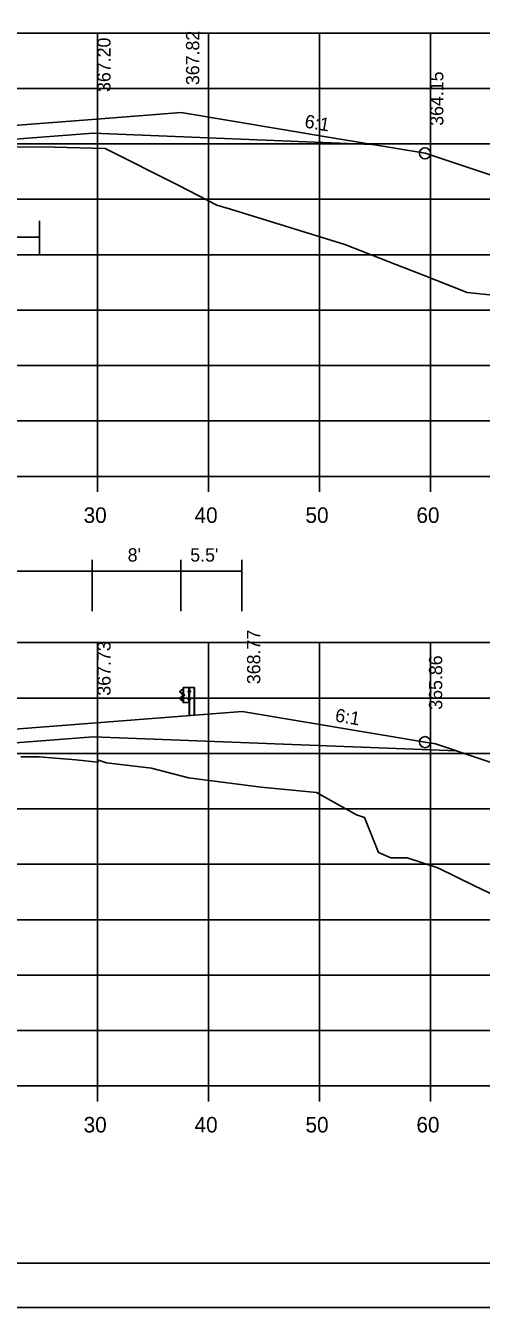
# Model space of a CAD drawing. Extents: x 1374859 to 1376773, y 382242 to 389804.
# Drawn here: x 1376158.1 to 1376199.2, y 384161.8 to 384277.4 of the extents above; entities that cross this region are included whole.
import ezdxf

# ---------------------------------------------------------------- set-up
doc = ezdxf.new("R2010")
doc.units = 0
for name, color, linetype in [('R_Axis', 7, 'Continuous'), ('R_Axis Annot', 7, 'Continuous'), ('R_Border', 7, 'Continuous'), ('R_Border Notes', 7, 'Continuous'), ('R_Exist Surface', 7, 'Continuous'), ('R_Fin Surface', 7, 'Continuous'), ('R_Grid', 7, 'Continuous'), ('R_MOT', 7, 'Continuous'), ('R_No Plot', 7, 'Continuous'), ('R_Proposed Road', 7, 'Continuous'), ('R_Xsect Elev', 7, 'Continuous'), ('R_Xsect Slope', 7, 'Continuous')]:
    doc.layers.add(name, color=color, linetype=linetype)

msp = doc.modelspace()

# ---------------------------------------------------------------- linework, layer by layer
at = {"layer": 'R_Axis'}
for p, q in [((1375994.57, 384236.76), (1376274.57, 384236.76)), ((1376164.57, 384235.36), (1376164.57, 384236.76)), ((1376174.57, 384235.36), (1376174.57, 384236.76)), ((1376184.57, 384235.36), (1376184.57, 384236.76)), ((1376194.57, 384235.36), (1376194.57, 384236.76)), ((1375994.57, 384181.76), (1376274.57, 384181.76)), ((1376164.57, 384180.36), (1376164.57, 384181.76)), ((1376174.57, 384180.36), (1376174.57, 384181.76)), ((1376184.57, 384180.36), (1376184.57, 384181.76)), ((1376194.57, 384180.36), (1376194.57, 384181.76))]:
    msp.add_line(p, q, dxfattribs=at)
at = {"layer": 'R_Border'}
msp.add_line((1376292.75, 384165.76), (1375976.57, 384165.76), dxfattribs=at)
at = {"layer": 'R_Border Notes'}
for points in [[(1376159.34, 384259.83), (1376159.34, 384256.83)], [(1376135.33, 384258.33), (1376159.34, 384258.33)]]:
    msp.add_lwpolyline(points, dxfattribs=at)
at = {"layer": 'R_Exist Surface'}
for points in [[(1376157.2, 384266.45), (1376159.53, 384266.49), (1376162.96, 384266.41), (1376165.25, 384266.35), (1376171.88, 384262.99), (1376175.32, 384261.23), (1376176.54, 384260.87), (1376186.87, 384257.69), (1376191.47, 384255.88), (1376193.87, 384254.93), (1376197.9, 384253.35), (1376203.67, 384252.75)], [(1376157.66, 384211.44), (1376158.17, 384211.44), (1376159.3, 384211.44), (1376162.61, 384211.18), (1376164.59, 384210.97), (1376164.65, 384211.16), (1376165.38, 384210.92), (1376169.44, 384210.43), (1376172.76, 384209.56), (1376179.31, 384208.72), (1376184.3, 384208.22), (1376187.91, 384206.23), (1376188.63, 384205.98), (1376189.88, 384202.82), (1376191, 384202.33), (1376192.48, 384202.35), (1376195.23, 384201.43), (1376198.56, 384199.8), (1376201.65, 384198.33)]]:
    msp.add_lwpolyline(points, dxfattribs=at)
at = {"layer": 'R_Fin Surface'}
for points in [[(1376036.23, 384252.25), (1376043.08, 384249.96), (1376075.09, 384260.63), (1376077.63, 384261.05), (1376091.59, 384263.38), (1376105.09, 384264.42), (1376134.59, 384266.69), (1376164.09, 384268.96), (1376172.09, 384269.58), (1376185.9, 384267.28), (1376194.09, 384265.91), (1376235.64, 384252.06)], [(1376077.63, 384261.05), (1376099.92, 384262.77), (1376129.4, 384265.04), (1376134.9, 384265.46), (1376164.18, 384267.72), (1376189.32, 384266.71)], [(1376040.72, 384196.37), (1376047.35, 384194.16), (1376075.09, 384203.41), (1376086.7, 384207.28), (1376091.59, 384208.91), (1376105.09, 384209.95), (1376134.59, 384212.22), (1376164.09, 384214.49), (1376177.59, 384215.53), (1376194.09, 384212.78), (1376195.04, 384212.62), (1376247.44, 384195)], [(1376086.7, 384207.28), (1376098.83, 384208.22), (1376128.31, 384210.49), (1376133.81, 384210.91), (1376164.18, 384213.25), (1376196.96, 384211.98)]]:
    msp.add_lwpolyline(points, dxfattribs=at)
at = {"layer": 'R_Grid'}
for p, q in [((1375994.57, 384276.76), (1376274.57, 384276.76)), ((1376164.57, 384236.76), (1376164.57, 384276.76)), ((1376174.57, 384236.76), (1376174.57, 384276.76)), ((1376184.57, 384236.76), (1376184.57, 384276.76)), ((1376194.57, 384236.76), (1376194.57, 384276.76)), ((1375994.57, 384271.76), (1376274.57, 384271.76)), ((1375994.57, 384266.76), (1376274.57, 384266.76)), ((1375994.57, 384261.76), (1376274.57, 384261.76)), ((1375994.57, 384256.76), (1376274.57, 384256.76)), ((1375994.57, 384251.76), (1376274.57, 384251.76)), ((1375994.57, 384246.76), (1376274.57, 384246.76)), ((1375994.57, 384241.76), (1376274.57, 384241.76)), ((1375994.57, 384236.76), (1376274.57, 384236.76)), ((1375994.57, 384221.76), (1376274.57, 384221.76)), ((1376164.57, 384181.76), (1376164.57, 384221.76)), ((1376174.57, 384181.76), (1376174.57, 384221.76)), ((1376184.57, 384181.76), (1376184.57, 384221.76)), ((1376194.57, 384181.76), (1376194.57, 384221.76)), ((1375994.57, 384216.76), (1376274.57, 384216.76)), ((1375994.57, 384211.76), (1376274.57, 384211.76)), ((1375994.57, 384206.76), (1376274.57, 384206.76)), ((1375994.57, 384201.76), (1376274.57, 384201.76)), ((1375994.57, 384196.76), (1376274.57, 384196.76)), ((1375994.57, 384191.76), (1376274.57, 384191.76)), ((1375994.57, 384186.76), (1376274.57, 384186.76)), ((1375994.57, 384181.76), (1376274.57, 384181.76))]:
    msp.add_line(p, q, dxfattribs=at)
at = {"layer": 'R_MOT'}
for p, q in [((1376164.07, 384224.59), (1376164.07, 384229.22)), ((1376172.07, 384224.59), (1376172.07, 384229.22)), ((1376177.57, 384224.59), (1376177.57, 384229.22)), ((1376091.57, 384228.22), (1376177.57, 384228.22))]:
    msp.add_line(p, q, dxfattribs=at)
at = {"layer": 'R_No Plot'}
msp.add_line((1375964.17, 384161.78), (1376297.5, 384161.78), dxfattribs=at)
for points in [[(1375964.16, 384375.12), (1376297.5, 384375.12), (1376297.5, 384161.78), (1375964.16, 384161.78)], [(1376210.49, 384371.22), (1376210.49, 384361.34), (1376246.22, 384361.34), (1376246.22, 384358.42), (1376269.42, 384358.42), (1376269.42, 384334.09), (1376292.75, 384334.09), (1376292.75, 384165.76), (1375976.57, 384165.76), (1375976.57, 384371.22)]]:
    msp.add_lwpolyline(points, close=True, dxfattribs=at)
for centre in [(1376194.09, 384265.91), (1376194.09, 384212.78)]:
    msp.add_circle(centre, 0.5, dxfattribs=at)
at = {"layer": 'R_Proposed Road'}
for p, q in [((1376172.3, 384216.35), (1376172.3, 384217.71)), ((1376172.8, 384217.72), (1376172.81, 384217.72)), ((1376172.8, 384217.72), (1376172.87, 384217.72)), ((1376172.83, 384215.2), (1376172.83, 384217.72)), ((1376173.29, 384217.72), (1376173.29, 384215.2)), ((1376173.32, 384217.72), (1376173.32, 384215.2)), ((1376172.15, 384216.55), (1376172.02, 384216.66)), ((1376172.03, 384217.4), (1376172.16, 384217.5)), ((1376172.2, 384217.15), (1376172.03, 384217.25)), ((1376172.04, 384217.38), (1376172.17, 384217.49)), ((1376172.21, 384217.17), (1376172.04, 384217.28)), ((1376172.16, 384216.57), (1376172.04, 384216.68)), ((1376172.05, 384216.82), (1376172.21, 384216.92)), ((1376172.06, 384216.8), (1376172.22, 384216.9)), ((1376172.26, 384216.49), (1376172.15, 384216.55)), ((1376172.16, 384217.5), (1376172.27, 384217.56)), ((1376172.27, 384216.51), (1376172.16, 384216.57)), ((1376172.17, 384217.49), (1376172.26, 384217.54)), ((1376172.24, 384216.97), (1376172.24, 384217.1)), ((1376172.26, 384216.97), (1376172.26, 384217.1)), ((1376172.31, 384216.97), (1376172.31, 384217.09)), ((1376172.31, 384217.09), (1376172.36, 384217.09)), ((1376172.31, 384217.06), (1376172.36, 384217.06)), ((1376172.31, 384217), (1376172.36, 384217)), ((1376172.31, 384217), (1376172.36, 384217)), ((1376172.31, 384216.97), (1376172.36, 384216.97)), ((1376172.37, 384216.98), (1376172.37, 384217.08)), ((1376172.79, 384217.41), (1376172.74, 384217.41)), ((1376172.74, 384217.41), (1376172.74, 384217.29)), ((1376172.74, 384217.35), (1376172.8, 384217.35)), ((1376172.79, 384217.29), (1376172.74, 384217.29)), ((1376172.74, 384216.6), (1376172.74, 384216.73)), ((1376172.74, 384216.73), (1376172.79, 384216.73)), ((1376172.74, 384216.66), (1376172.8, 384216.66)), ((1376172.74, 384216.6), (1376172.79, 384216.6)), ((1376172.87, 384217.29), (1376172.87, 384217.42)), ((1376172.87, 384217.42), (1376172.92, 384217.42)), ((1376172.87, 384217.39), (1376172.92, 384217.39)), ((1376172.87, 384217.32), (1376172.91, 384217.32)), ((1376172.87, 384217.32), (1376172.92, 384217.32)), ((1376172.87, 384217.29), (1376172.92, 384217.29)), ((1376172.88, 384216.6), (1376172.88, 384216.73)), ((1376172.88, 384216.73), (1376172.93, 384216.73)), ((1376172.88, 384216.7), (1376172.93, 384216.7)), ((1376172.88, 384216.63), (1376172.92, 384216.63)), ((1376172.88, 384216.63), (1376172.93, 384216.63)), ((1376172.88, 384216.6), (1376172.93, 384216.6)), ((1376172.92, 384217.31), (1376172.92, 384217.4)), ((1376172.93, 384216.62), (1376172.93, 384216.71)), ((1376172.8, 384216.35), (1376172.83, 384216.35))]:
    msp.add_line(p, q, dxfattribs=at)
for points in [[(1376172.27, 384217.72), (1376172.28, 384216.35), (1376172.8, 384216.35), (1376172.8, 384217.72)], [(1376172.31, 384217.11), (1376172.31, 384216.95), (1376172.3, 384216.95), (1376172.3, 384217.11)], [(1376172.37, 384217.06), (1376172.37, 384217), (1376172.4, 384217), (1376172.4, 384217.06)], [(1376172.74, 384217.41), (1376172.74, 384217.29), (1376172.8, 384217.29), (1376172.8, 384217.41)], [(1376172.74, 384216.73), (1376172.74, 384216.6), (1376172.8, 384216.6), (1376172.8, 384216.73)], [(1376172.87, 384217.44), (1376172.87, 384217.27), (1376172.86, 384217.27), (1376172.86, 384217.44)], [(1376172.88, 384216.75), (1376172.88, 384216.58), (1376172.87, 384216.58), (1376172.87, 384216.75)], [(1376172.93, 384217.38), (1376172.93, 384217.32), (1376172.95, 384217.32), (1376172.95, 384217.38)], [(1376172.94, 384216.7), (1376172.94, 384216.63), (1376172.96, 384216.63), (1376172.96, 384216.7)]]:
    msp.add_lwpolyline(points, close=True, dxfattribs=at)
msp.add_lwpolyline([(1376173.32, 384217.72), (1376172.87, 384217.72), (1376172.87, 384215.2)], dxfattribs=at)
for centre, radius, start, end in [((1376172.07, 384217.33), 0.0856, 122.0217, 240.7501), ((1376172.11, 384216.73), 0.109, 120.88, 214.7816), ((1376172.07, 384217.33), 0.062, 122.0217, 240.7501), ((1376172.11, 384216.73), 0.0854, 120.88, 214.7816), ((1376172.17, 384217.09), 0.0622, 4.9556, 61.894), ((1376172.24, 384217.03), 0.0453, 93.9303, 257.0446), ((1376172.17, 384217.09), 0.0865, 4.9556, 61.894), ((1376172.19, 384216.96), 0.0462, 293.1464, 8.2196), ((1376172.19, 384216.96), 0.0703, 293.1464, 8.2196), ((1376172.35, 384217.08), 0.022, 317.7756, 45.4255), ((1376172.28, 384217.03), 0.0922, 339.7423, 20.2577), ((1376172.34, 384216.98), 0.025, 323.3766, 39.0666), ((1376172.9, 384217.4), 0.022, 317.7756, 45.4255), ((1376172.83, 384217.35), 0.0922, 339.7423, 20.2577), ((1376172.9, 384217.31), 0.025, 323.3766, 39.0666), ((1376172.91, 384216.71), 0.022, 317.7756, 45.4255), ((1376172.84, 384216.66), 0.0922, 339.7423, 20.2577), ((1376172.91, 384216.62), 0.025, 323.3766, 39.0666)]:
    msp.add_arc(centre, radius, start, end, dxfattribs=at)

# ---------------------------------------------------------------- texts
at = {"layer": 'R_Axis Annot'}
for s, p in [('30', (1376163.31, 384232.56)), ('40', (1376173.31, 384232.56)), ('50', (1376183.31, 384232.56)), ('60', (1376193.31, 384232.56)), ('30', (1376163.31, 384177.56)), ('40', (1376173.31, 384177.56)), ('50', (1376183.31, 384177.56)), ('60', (1376193.31, 384177.56))]:
    msp.add_text(s, height=1.4, dxfattribs=at).set_placement(p)
at = {"layer": 'R_MOT'}
for s, p in [("8'", (1376167.28, 384229.07)), ("5.5'", (1376172.92, 384229.07))]:
    msp.add_text(s, height=1.2, dxfattribs=at).set_placement(p)
at = {"layer": 'R_Xsect Elev'}
for s, p in [('367.82', (1376173.74, 384272.06)), ('367.20', (1376165.74, 384271.44)), ('364.15', (1376195.74, 384268.39)), ('368.77', (1376179.24, 384218.01)), ('367.73', (1376165.74, 384216.97)), ('365.86', (1376195.64, 384215.7))]:
    msp.add_text(s, height=1.2, rotation=90, dxfattribs=at).set_placement(p)
at = {"layer": 'R_Xsect Slope'}
for p in [(1376183.17, 384268.24), (1376185.92, 384214.65)]:
    msp.add_text('6:1', height=1.2, rotation=350.5358, dxfattribs=at).set_placement(p)

doc.saveas('drawing.dxf')
